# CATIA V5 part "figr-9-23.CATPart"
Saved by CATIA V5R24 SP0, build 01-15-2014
Part number: Part2
Bounding box of the stored display mesh (mm): x -72 to 72, y -80 to 90, z -20 to 41.296
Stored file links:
  D:\KAVITA\CATIA V5-6R2014 Project_ Kavita\CATIA V5-6R2014_partfiles\Partfiles\c09_catia_v5-6r2014_prt\figr-9-23.CATPart
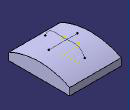
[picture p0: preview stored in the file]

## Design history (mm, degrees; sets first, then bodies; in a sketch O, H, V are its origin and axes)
Body1 (main body)
  Sketch1 on yz-plane, origin (0, 0, 0), H (0, 1, 0), V (0, 0, 1)
    arc A1 centre (5, -170) radius 190.0658 from (-80, 0) to (90, 0) cw
    point P2 (-80, 0)
    point P3 (0, 20)
    line L1 (-80, 0) -> (-80, -20)
    line L2 (-80, -20) -> (90, -20)
    line L3 (90, -20) -> (90, 0)
    coincidence: P2 H, A1 P3, P3 V
    vertical: L1 V, L3 V
    horizontal: L2 H
  Pad1: profile Sketch1, direction (1, 0, 0), length 72, mirrored extent
  Sketch2 on zx-plane, origin (0, 0, 0), H (-1, 0, 0), V (0, 0, 1)
    line L1 (-40, 30) -> (40, 30)
    horizontal: L1 H
  Sketch3 on yz-plane, origin (0, 0, 0), H (0, 1, 0), V (0, 0, 1)
    spline S1 through (60, 20) (40, 40) (10, 40) (-10, 40) (-30, 40) (-50, 20)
